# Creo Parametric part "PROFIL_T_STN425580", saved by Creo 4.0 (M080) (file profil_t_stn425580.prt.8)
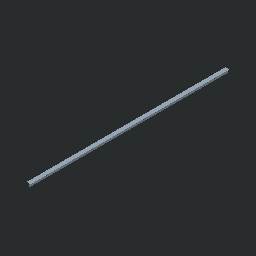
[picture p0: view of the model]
Units: millimeter Kilogram Sec (mmKs); MM, KILOGRAM, SECS
Materials in the file: OCEL_N

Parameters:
  MFG_WP_MATERIAL = "OCEL"
  NAZOV = "PROFIL_T_STN425580"
  NORMA = "STN 42 5580"
  PTC_MATERIAL_NAME = "OCEL_N"

Other parameters: HMOTNOST, HUSTOTA, D1, D3, D4, D6, D7, D12, D11, D2, D5, D14

Created from: T.PRT

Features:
  1. datum plane "DTM1"

Layers: 1, 2, 3, 4, 5, 6, 7, 8, 9, 10, 11, 12, 13, 14, 15, 16, 17, 18, 19, 20, 21, 22, 23, 24, 25, 26, 27, 28, 29, 30, 31, 32

Family table entries: GENERIC, PROFIL_T_20, PROFIL_T_STN425580, value(d_val), 2/4, value(i_val), PROFIL_T_25, PROFIL_T_STN425580, !/9, 2/9, PROFIL_T_30, PROFIL_T_STN425580, !/>, 2/>, PROFIL_T_35, PROFIL_T_STN425580, PROFIL_T_50, PROFIL_T_STN425580, !/I, 2/I, PROFIL_T_60, PROFIL_T_STN425580, !/N, 2/N, PROFIL_T_80, PROFIL_T_STN425580, !/T, 2/T, 2/!, 2/!, PROFIL_T_80X60, PROFIL_T_STN425580, !/T, 2/N, 2/", 2/", # Pro/TABLE, [] S 92;, [] W 10;, [A] W  3;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

Surfaces: 10 plane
